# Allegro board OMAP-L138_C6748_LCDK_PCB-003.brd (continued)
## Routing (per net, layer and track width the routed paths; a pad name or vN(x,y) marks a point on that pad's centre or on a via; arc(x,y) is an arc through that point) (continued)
DDR_DQ0: length 21.6
  TOP w0.121: v1(38.61,32) 37.34,33.27 37.34,37.59 36.43,38.5 35.76,38.5 U17.G8
  LYR3 w0.133: v1(38.61,32) 39.62,30.99 44.45,30.99 46.48,28.96 v1(49.53,28.96)
  BOTTOM w0.121: R107.1 v1(49.53,28.96)
DDR_DQ1: length 21.5
  TOP w0.254: v1(40.56,38.5) U17.G2
  LYR3 w0.133: v1(49.53,29.97) 51.05,31.5 51.05,37.97 50.93,38.1 45.72,38.1 44.83,38.99 43.94,38.99 43.43,38.48 42.04,38.48 41.48,39.04 41.1,39.04 v1(40.56,38.5)
  BOTTOM w0.121: R108.1 v1(49.53,29.97)
DDR_DQ2: length 21
  TOP w0.121: U17.H7 36.83,39.7 36.96,39.83 36.96,40.39 37.08,40.51 37.59,40.51 37.72,40.39 37.72,33.53 40.39,30.86 44.32,30.86 46.74,28.45 R109.1
DDR_DQ3: length 21.3
  TOP w0.254: U17.H3 v1(39.76,39.3)
  LYR3 w0.121: 41.76,38.1 40.39,38.1 40.16,38.33 40.16,38.9 v1(39.76,39.3)
  LYR3 w0.133: 41.76,38.1 41.76,38.09 44.33,38.09 44.33,38.1 45.17,38.1 45.68,37.59 50.55,37.59 50.67,37.47 50.67,31.75 50.04,31.11 49.66,31.11 49.53,31.24 v1(49.53,32)
  BOTTOM w0.121: R110.1 v1(49.53,32)
DDR_DQ4: length 21.2
  TOP w0.121: U17.H1 41.91,38.75 41.91,32.77 42.04,32.64 42.42,32.64 42.55,32.77 42.55,33.78 42.67,33.91 43.05,33.91 43.18,33.78 43.18,32.77 43.31,32.64 44.45,32.64 44.58,32.51 44.58,32.26 44.45,32.13 42.29,32.13 42.16,32 42.16,31.75 42.29,31.62 45.34,31.62 46.48,30.48 R111.1
DDR_DQ5: length 21.5
  TOP w0.121: R112.1 v1(45.97,32.51)
  TOP w0.254: U17.H9 v1(34.16,39.3)
  LYR3 w0.133: v1(45.97,32.51) 34.04,32.51 33.27,33.27 33.27,38.42 v1(34.16,39.3)
DDR_DQ6: length 21.1
  TOP w0.121: R115.1 45.97,31.5 45.09,32.38 45.09,32.89 44.96,33.02 43.69,33.02 43.56,33.15 43.56,35.81 43.69,35.94 44.96,35.94 45.09,36.07 45.09,36.36 44.96,36.48 43.31,36.48 43.18,36.61 43.18,37.47 43.31,37.59 45.85,37.59 45.97,37.47 v1(45.97,37.08)
  TOP w0.254: v1(41.36,37.7) U17.F1
  LYR3 w0.121: 41.76,37.71 41.36,37.71 v1(41.36,37.7)
  LYR3 w0.133: v1(45.97,37.08) 45.64,37.08 45.02,37.71 41.76,37.71
DDR_DQ7: length 21.4
  TOP w0.121: R116.1 v1(46.74,33.53)
  TOP w0.254: U17.F9 v1(34.16,37.7)
  LYR3 w0.133: v1(46.74,33.53) 46.74,33.15 46.61,33.02 45.47,33.02 45.34,32.89 36.32,32.89 36.2,33.02 36.2,33.15 36.07,33.27 35.81,33.27 35.69,33.15 35.69,33.03 35.56,32.9 35.31,32.9 35.18,33.03 35.18,33.15 35.05,33.27 34.8,33.27 34.67,33.15 34.67,33.03 34.54,32.9 34.28,32.9 33.66,33.53 33.66,37.97 33.78,38.1 34.03,38.1 34.16,37.97 v1(34.16,37.7)
DDR_DQ8: length 21.4
  TOP w0.254: U17.C8 v1(34.96,35.3)
  LYR3 w0.121: v1(34.96,35.3) 35.36,34.9 36.04,34.9 ; 41.76,34.9 40.28,34.9 40.16,35.03 40.16,35.66 40.01,35.81 39.5,35.81
  LYR3 w0.133: 36.04,34.9 36.96,35.81 39.5,35.81 ; 41.76,34.9 41.77,34.89 45.53,34.89 45.59,34.95 46.96,34.95 47.24,34.67 47.24,32.13 47.12,32 v1(46.74,32)
  BOTTOM w0.121: R138.1 49.53,30.99 48.51,32 v1(46.74,32)
DDR_DQ9: length 21.1
  TOP w0.254: v1(40.56,35.3) U17.C2
  LYR3 w0.121: v1(40.56,35.3) 40.96,35.7 41.76,35.7
  LYR3 w0.133: v1(49.53,34.04) 48.39,34.04 48.26,33.91 48.26,30.99 48.13,30.86 46.23,30.86 46.1,30.99 46.1,31.37 46.23,31.5 47.62,31.5 47.75,31.62 47.75,35.2 47.62,35.33 44.81,35.33 44.42,35.71 41.77,35.71 41.76,35.7
  BOTTOM w0.121: R140.1 v1(49.53,34.04)
DDR_DQ10: length 21.4
  TOP w0.254: v1(35.76,36.1) U17.D7
  LYR3 w0.121: 35.36,38.35 35.36,36.5 v1(35.76,36.1) ; 45.19,36.83 44.7,37.32 41.74,37.32 41.72,37.3 39.5,37.3
  LYR3 w0.133: v1(46.74,37.08) 46.23,36.58 45.45,36.58 45.19,36.83 ; 35.36,38.35 35.48,38.48 37.21,38.48 37.34,38.35 37.34,37.72 37.47,37.59 37.85,37.59 37.97,37.72 37.97,38.35 38.1,38.48 39.22,38.48 39.35,38.35 39.35,37.45 39.5,37.3
  BOTTOM w0.121: R224.1 49.53,38.1 48.51,37.08 v1(46.74,37.08)
DDR_DQ11: length 21.5
  TOP w0.121: U17.D3 38.48,35.62 38.48,33.78 40.25,32.01 v1(40.64,32.01)
  LYR3 w0.133: v1(40.64,32.01) 40.13,32.01 40.01,31.88 40.01,31.5 40.13,31.37 44.61,31.37 46.64,29.34 48.77,29.34 49.02,29.58 49.02,32.51 v1(49.53,33.02)
  BOTTOM w0.121: R225.1 v1(49.53,33.02)
DDR_DQ12: length 21.5
  TOP w0.254: v1(41.36,36.1) U17.D1
  LYR3 w0.121: 41.76,36.1 v1(41.36,36.1)
  LYR3 w0.133: 41.76,36.1 44.54,36.1 44.98,35.66 46.75,35.66 46.8,35.71 48.13,35.71 48.26,35.59 48.26,34.67 48.39,34.54 48.9,34.54 49.02,34.67 49.02,36.45 49.15,36.58 50.16,36.58 50.29,36.7 R226.1 50.16,37.21 47.62,37.21 47.5,37.08 47.5,36.7 47.37,36.58 46.86,36.58 46.74,36.45 v1(46.74,36.1)
  BOTTOM w0.121: R226.1 49.53,37.08 48.55,36.1 v1(46.74,36.1)
DDR_DQ13: length 21.4
  TOP w0.121: R227.1 46.48,36.58 v1(45.97,36.07)
  TOP w0.254: U17.D9 v1(34.16,36.1)
  LYR3 w0.121: 41.66,36.49 41.65,36.5 39.58,36.5 ; v1(34.16,36.1) 34.56,35.7 36.16,35.7
  LYR3 w0.133: 36.16,35.7 36.28,35.83 36.28,37.97 36.41,38.1 36.7,38.1 36.83,37.97 36.83,36.45 36.96,36.32 38.35,36.32 38.48,36.45 38.48,37.97 38.61,38.1 38.86,38.1 38.99,37.97 38.99,36.63 39.12,36.5 39.58,36.5 ; 41.66,36.49 43.99,36.49 44.79,36.49 45.21,36.07 v1(45.97,36.07)
DDR_DQ14: length 21.5
  TOP w0.254: v1(41.36,34.5) U17.B1
  LYR3 w0.121: 41.76,34.5 v1(41.36,34.5)
  LYR3 w0.133: v1(45.97,34.54) 45.93,34.5 41.76,34.5
  BOTTOM w0.121: v1(45.97,34.54) 45.97,35.43 46.1,35.56 47.37,35.56 47.5,35.43 47.5,32.64 47.62,32.51 47.88,32.51 48.01,32.64 48.01,35.43 48.13,35.56 48.39,35.56 48.51,35.43 48.51,32.64 48.64,32.51 48.9,32.51 49.02,32.64 49.02,34.92 49.15,35.05 R228.1
DDR_DQ15: length 21.4
  TOP w0.121: v1(45.97,33.53) 44.78,33.53 44.7,33.6 44.7,33.83 44.78,33.91 45.39,33.91 45.47,33.99 45.47,34.21 45.39,34.29 44.91,34.29 44.83,34.37 44.83,34.72 44.91,34.8 45.39,34.8 45.47,34.87 45.47,35.1 45.39,35.18 44.78,35.18 44.7,35.26 44.7,35.48 44.78,35.56 R229.1
  TOP w0.254: U17.B9 v1(34.16,34.5)
  LYR3 w0.121: 36.8,33.3 36,34.1 34.56,34.1 v1(34.16,34.5)
  LYR3 w0.133: 36.8,33.3 36.83,33.27 44.96,33.27 45.21,33.53 v1(45.97,33.53)
DDR_DQGATE0: length 28.3
  TOP w0.254: v1(56.56,36.9) U7.R11
  LYR3 w0.121: v1(56.56,36.9) 56.16,37.3 55.59,37.3 55.36,37.53 55.36,37.87 53.76,39.47
  LYR3 w0.133: 53.76,39.47 52.58,40.65 52.58,45.47 49.02,49.02 38.35,49.02 38.1,48.77 38.1,48.51 38.23,48.39 v1(38.27,48.39)
  BOTTOM w0.121: R53.1 v1(38.27,48.39)
DDR_DQGATE1: length 29.7
  TOP w0.254: v1(57.36,36.9) U7.R12
  LYR3 w0.121: 53.76,39.84 55.5,38.1 55.88,38.1 55.93,38.1 56.66,37.36 56.9,37.36 v1(57.36,36.9)
  LYR3 w0.133: 53.76,39.84 52.83,40.77 52.83,45.59 49.15,49.28 38.14,49.28 v1(37.25,48.39)
  BOTTOM w0.121: R53.2 v1(37.25,48.39)
DDR_DQM0: length 21.4
  TOP w0.121: R136.2 46.48,29.46 44.7,31.24 40.51,31.24 38.1,33.66 38.1,40.39 38.23,40.51 38.61,40.51 38.73,40.39 38.73,38.23 38.86,38.1 U17.F3
DDR_DQM1: length 21.4
  TOP w0.121: U17.B3 38.99,34.9 38.86,34.77 38.86,33.91 40.01,32.77 40.64,32.77 v1(41.4,32)
  LYR3 w0.133: v1(41.4,32) 44.51,32 46.04,30.48 47.37,30.48 47.5,30.35 47.5,29.84 47.62,29.72 48.51,29.72 48.64,29.84 48.64,32.93 49.23,33.53 49.78,33.53 50.04,33.78 50.04,35.56 v1(49.53,36.07)
  BOTTOM w0.121: R135.2 v1(49.53,36.07)
DDR_DQS0: length 21.1
  TOP w0.121: U17.F7 36.96,37.3 36.96,32.77 39.24,30.48 44.2,30.48 46.86,27.81 49.4,27.81 v1(49.53,27.94)
  BOTTOM w0.121: R134.2 v1(49.53,27.94)
DDR_DQS1: length 21.5
  TOP w0.121: R133.2 v1(46.74,34.54)
  TOP w0.254: v1(35.76,34.5) U17.B7
  LYR3 w0.121: 41.83,34.1 40.13,34.1
  LYR3 w0.133: 40.13,34.1 39.94,34.29 39.48,34.29 39.35,34.42 39.35,35.33 39.24,35.43 38.99,35.43 38.86,35.31 38.86,33.78 38.73,33.66 38.48,33.66 38.35,33.78 38.35,35.31 38.23,35.43 37.97,35.43 37.85,35.31 37.85,33.78 37.72,33.66 37.47,33.66 37.34,33.78 37.34,35.05 37.21,35.18 36.96,35.18 36.83,35.05 36.83,34.42 36.7,34.29 36.41,34.29 36.2,34.5 v1(35.76,34.5) ; v1(46.74,34.54) 46.74,34.23 46.61,34.11 43.31,34.11 43.18,33.98 43.18,33.78 43.05,33.66 42.42,33.66 42.29,33.78 42.29,33.98 42.16,34.11 41.83,34.11 41.83,34.1
DDR_RASN: length 18.8
  TOP w0.121: v1(45.97,38.61) 46.99,37.59 R128.2
  TOP w0.254: v1(35.76,41.7) U17.K7
  LYR3 w0.133: v1(45.97,38.61) 46.48,39.12 47.5,39.12 47.75,39.36 47.75,40.77 47.37,41.15 44.7,41.15 43.94,41.91 40.39,41.91 40.13,42.16 39.5,42.16 39.03,41.7 v1(35.76,41.7)
DDR_VREF: length 30.4
  TOP w0.254: v1(40.56,40.9) U17.J2 ; v1(56.56,41.7) U7.R6
  BOTTOM w0.457: 38.27,40.3 C119.1 R123.2 ; 38.27,40.3 R124.1 C136.2 39.05,42.1 39.37,42.42 43.69,42.42 45.21,43.94 45.21,47.37 47.37,49.53 52.32,49.53 54.16,47.69 v1(54.16,46.5) ; 38.27,40.3 40.31,40.3 40.56,40.54 v1(40.56,40.9)
DDR_WEN: length 18.7
  TOP w0.254: U17.K3 v1(39.76,41.7)
  LYR3 w0.121: 40.96,40.77 40.96,41.15
  LYR3 w0.133: v1(39.76,41.7) 39.93,41.53 40.77,41.53 40.96,41.34 40.96,41.15 ; 40.96,40.77 40.96,40.58 41.15,40.39 41.66,40.39 41.78,40.51 41.78,41.45 41.86,41.53 42.09,41.53 42.16,41.45 42.16,40.46 42.24,40.39 42.47,40.39 42.55,40.46 42.55,41.45 42.62,41.53 42.85,41.53 42.93,41.45 42.93,40.46 43,40.39 43.23,40.39 43.31,40.46 43.31,41.45 43.38,41.53 43.61,41.53 43.69,41.45 43.69,40.51 43.81,40.39 45.72,40.39 v1(45.97,40.64)
  BOTTOM w0.121: v1(45.97,40.64) 46.48,40.13 R129.2
DSP_CLKOUT: length 2
  TOP w0.121: TP10.1 55.63,21.08 R60.1
DSP_RSTOUTN: length 29
  TOP w0.121: v1(56.56,26.42) 57.15,27.01 57.15,27.56 57.78,28.19 66.29,28.19 68.07,26.42 70.36,26.42 73.98,30.04 U11.1
  TOP w0.254: v1(55.76,32.1) U7.T17
  BOTTOM w0.121: v1(56.56,26.42) 55.88,27.1 55.88,29.78 55.76,29.9 v1(55.76,32.1)
EMA_A0: length 51.1
  TOP w0.254: v1(66.96,34.5) U7.C14
  LYR3 w0.121: 68.96,34.5 v1(66.96,34.5)
  LYR3 w0.133: 68.96,34.5 71.59,34.5 71.59,34.51 71.93,34.51 71.94,34.5 74.04,34.5 74.25,34.29 v1(87.88,34.29)
  LYR4 w0.133: v1(87.88,34.29) 88.52,33.66 88.52,29.46 88.65,29.34 90.81,29.34 90.93,29.46 90.93,34.16 91.06,34.29 93.73,34.29 93.85,34.42 93.85,36.45 93.73,36.58 91.19,36.58 91.06,36.45 91.06,35.69 90.93,35.56 90.65,35.56 90.53,35.69 90.53,42.19 J14.21
EMA_A1: length 51.9
  TOP w0.121: v1(82.04,36.32) 82.55,36.83 90.68,36.83 v1(90.93,37.08)
  TOP w0.254: U18.C4 v1(80.96,52.5) ; v1(66.16,33.7) U7.D15
  LYR4 w0.133: J14.22 90.93,42.04 v1(90.93,37.08)
  BOTTOM w0.121: v1(66.16,33.7) 66.21,33.7 66.61,34.1 67.13,34.1 68.08,35.05 71.88,35.05 73.15,33.78 79.5,33.78 v1(82.04,36.32) ; J14.22 90.93,44.32 89.53,44.32 85.09,48.77 85.09,51.56 83.75,52.9 81.36,52.9 v1(80.96,52.5)
EMA_A2: length 54
  TOP w0.121: U7.B14 67.76,34.5 68.75,34.5 68.98,34.28 68.98,32.51 69.1,32.38 72.42,32.38 72.63,32.59 72.63,35.67 74.3,37.34 76.2,37.34 76.45,37.08 90.17,37.08 91.06,37.97 91.06,38.48 91.69,39.12 91.69,39.68 90.73,40.64 J14.23
  TOP w0.254: v1(80.16,53.3) U18.D5
  LYR3 w0.121: v1(80.16,53.3) 79.76,52.9 79.76,52.1
  LYR3 w0.133: v1(84.33,50.8) 84.33,50.83 83.34,51.82 80.04,51.82 79.76,52.1
  BOTTOM w0.121: J14.23 88.39,41.78 88.39,44.58 84.33,48.64 v1(84.33,50.8)
EMA_A3: length 52.5
  TOP w0.121: v1(87.88,33.53) 88.39,33.02 88.39,29.34 88.52,29.21 94.36,29.21 94.49,29.34 94.49,37.97 94.36,38.1 93.98,38.1 93.85,37.97 93.85,35.18 93.73,35.05 93.34,35.05 93.22,35.18 93.22,39.5 J14.24
  TOP w0.254: v1(66.16,34.5) U7.D14
  LYR3 w0.121: v1(66.16,34.5) 66.39,34.5 66.79,34.1 66.95,34.1 68.96,34.1
  LYR3 w0.133: 68.96,34.1 69.28,34.1 69.72,33.66 72.01,33.66 72.39,34.04 87.38,34.04 v1(87.88,33.53)
EMA_A4: length 50
  TOP w0.121: U7.A14 72.06,34.9 72.14,34.82 72.14,34.62 72.06,34.54 69.29,34.54 69.22,34.47 69.22,34.39 69.22,34.38 69.22,34.23 69.29,34.16 71.27,34.16 71.35,34.09 71.35,33.86 71.27,33.78 69.3,33.78 69.22,33.71 69.22,32.77 69.35,32.64 71.17,32.64 71.25,32.72 71.25,32.94 71.17,33.02 69.67,33.02 69.6,33.1 69.6,33.32 69.67,33.4 72.3,33.4 72.38,33.48 72.38,35.8 74.17,37.59 76.45,37.59 76.71,37.34 88.39,37.34 88.52,37.47 88.52,38.99 88.39,39.12 87.83,39.12 87.76,39.19 87.76,39.55 87.83,39.62 91.33,39.62 91.44,39.51 91.44,39.35 91.33,39.24 90.37,39.24 90.3,39.17 90.3,38.94 90.37,38.86 90.73,38.86 90.81,38.79 90.81,38.23 90.68,38.1 J14.25
EMA_A5: length 51.5
  TOP w0.254: v1(66.96,35.3) U7.C13
  LYR3 w0.121: v1(66.96,35.3) 68.58,35.3 68.71,35.43 68.71,37.85 68.96,38.1
  LYR3 w0.133: J14.26 92.08,36.96 92.2,36.83 93.85,36.83 93.98,36.7 93.98,32.13 93.85,32 93.73,32 93.6,32.13 93.6,36.2 93.47,36.32 93.22,36.32 93.09,36.2 93.09,32.13 92.96,32 90.81,32 90.68,32.13 90.68,35.94 89.92,36.7 88.77,36.7 88.35,37.12 72.39,37.12 72.26,37.25 72.26,37.97 72.14,38.1 71.94,38.1 71.93,38.11 71.59,38.11 71.59,38.1 69.54,38.1 69.53,38.11 69.19,38.11 69.19,38.1 68.96,38.1
EMA_A6: length 51.6
  TOP w0.254: v1(65.36,35.3) U7.E13
  LYR3 w0.121: v1(65.36,35.3) 65.76,34.9 67.28,34.9 67.31,34.92 68.96,34.92
  LYR3 w0.133: 68.96,34.92 74.04,34.92 74.17,35.05 74.17,35.43 74.04,35.56 69.22,35.56 69.09,35.69 69.09,35.94 69.22,36.07 69.72,36.07 69.85,36.2 69.85,37.72 69.98,37.85 70.23,37.85 70.36,37.72 70.36,36.14 70.43,36.07 70.66,36.07 70.74,36.14 70.74,37.72 70.87,37.85 71.12,37.85 71.25,37.72 71.25,36.2 71.37,36.07 78.11,36.07 78.23,35.94 78.23,35.18 78.11,35.05 74.8,35.05 74.68,34.92 74.68,34.67 74.8,34.54 87.25,34.54 87.5,34.8 87.5,35.31 87.76,35.56 J14.27
EMA_A7: length 50.9
  TOP w0.121: v1(87.88,38.35) 87.88,37.72 87.76,37.59 76.96,37.59 76.71,37.85 74.04,37.85 72.14,35.94 72.14,35.91 72.13,35.91 72.13,35.42 72.01,35.3 67.76,35.3 U7.B13
  BOTTOM w0.121: v1(87.88,38.35) 87.88,39.04 87.96,39.12 90.6,39.12 90.68,39.04 90.68,37.67 90.75,37.59 90.98,37.59 91.06,37.67 91.06,39.04 91.14,39.12 93.22,39.12 93.47,38.86 93.47,31.57 93.4,31.5 93.17,31.5 93.09,31.57 93.09,33.96 93.01,34.04 91.52,34.04 91.44,34.11 91.44,34.47 91.52,34.54 93.01,34.54 93.09,34.62 93.09,37.01 93.01,37.08 92.15,37.08 92.08,37.01 J14.28
EMA_A8: length 50.3
  TOP w0.121: v1(86.36,38.35) 86.36,38.48 86.23,38.61 78.56,38.61 78.49,38.53 78.49,38.3 78.56,38.23 85.78,38.23 85.85,38.15 85.85,37.92 85.78,37.85 77.55,37.85 77.47,37.92 77.47,38.53 77.39,38.61 77.17,38.61 77.09,38.53 77.09,38.18 77.01,38.1 76.78,38.1 76.71,38.18 76.71,38.53 76.63,38.61 76.4,38.61 76.33,38.53 76.33,38.18 76.25,38.1 76.02,38.1 75.95,38.18 75.95,38.53 75.87,38.61 75.64,38.61 75.56,38.53 75.56,38.18 75.49,38.1 75.26,38.1 75.18,38.18 75.18,38.53 75.11,38.61 74.93,38.61 74.42,38.1 73.36,38.1 73.28,38.02 73.28,37.54 73.2,37.47 73.1,37.47 73.03,37.54 73.03,38.02 72.95,38.1 72.85,38.1 72.77,38.02 72.77,37.16 72.69,37.08 72.59,37.08 72.52,37.16 72.52,38.02 72.44,38.1 72.34,38.1 72.26,38.02 72.26,37.16 72.19,37.08 71.32,37.08 71.25,37.01 71.25,36.02 71.32,35.94 71.81,35.94 71.88,35.86 71.88,35.64 71.81,35.56 68.74,35.56 68.6,35.7 U7.A13
  BOTTOM w0.121: v1(86.36,38.35) 86.36,37.85 88.39,35.81 88.39,35.18 89.53,34.04 J14.29
EMA_A9: length 52.2
  TOP w0.254: v1(66.16,36.1) U7.D12
  LYR3 w0.121: v1(66.16,36.1) 66.56,35.7 68.33,35.7 68.45,35.83 68.45,38.23 68.58,38.35 68.96,38.35
  LYR3 w0.133: 68.96,38.35 76.07,38.35 76.2,38.23 76.2,37.97 76.07,37.85 72.77,37.85 72.64,37.72 72.64,37.48 72.77,37.36 77.12,37.36 77.12,37.36 77.31,37.36 77.31,37.36 78.76,37.36 80.26,38.86 88.39,38.86 88.52,38.73 88.52,37.97 88.39,37.85 83.44,37.85 83.31,37.72 83.31,37.48 83.44,37.36 88.63,37.36 88.9,37.08 90.04,37.08 91.06,36.07 91.06,34.04 J14.30
EMA_A10: length 51
  TOP w0.254: v1(66.96,36.1) U7.C12
  LYR3 w0.121: v1(66.96,36.1) 66.96,36.96 67.09,37.08 68.07,37.08 68.2,37.21 68.2,38.42 68.39,38.61 68.96,38.61
  LYR3 w0.133: J14.31 90.55,31.5 94.74,31.5 94.87,31.62 94.87,33.91 95,34.04 96.39,34.04 96.52,34.16 96.52,34.42 96.39,34.54 95,34.54 94.87,34.67 94.87,36.45 95,36.58 96.39,36.58 96.52,36.7 96.52,36.96 96.39,37.08 95,37.08 94.87,37.21 94.87,38.99 94.74,39.12 80.01,39.12 78.49,37.59 77.22,37.59 76.2,38.61 68.96,38.61
EMA_A11: length 51.7
  TOP w0.121: v1(87.12,38.35) 87.12,38.73 87,38.86 74.68,38.86 74.17,38.35 71.7,38.35 70.87,37.52 70.87,36.83 69.85,35.81 68.87,35.81 68.58,36.1 67.76,36.1 U7.B12
  BOTTOM w0.121: J14.32 93.85,30.48 93.98,30.35 93.98,23.5 93.85,23.37 93.34,23.37 93.22,23.5 93.22,26.29 93.09,26.42 91.19,26.42 91.06,26.54 91.06,36.33 90.81,36.58 88.39,36.58 87.12,37.85 v1(87.12,38.35)
EMA_A12: length 52.5
  TOP w0.254: v1(66.16,35.3) U7.D13
  LYR4 w0.133: v1(81.28,36.32) 80.64,35.69 80.64,19.3 80.9,19.05 87.63,19.05 87.88,19.3 87.88,27.69 88.14,27.94 J14.33
  BOTTOM w0.121: v1(66.16,35.3) 66.56,34.9 67.13,34.9 67.53,35.31 72.14,35.31 73.41,34.04 79.25,34.04 81.28,36.07 v1(81.28,36.32)
EMA_BA_0: length 51
  TOP w0.254: v1(66.96,33.7) U7.C15
  LYR3 w0.121: v1(66.96,33.7) 67.36,33.3 67.36,30.18 67.44,30.1
  LYR3 w0.133: J14.37 89.53,23.75 89.41,23.88 83.69,23.88 83.57,24 83.57,24.26 83.69,24.38 93.34,24.38 93.47,24.51 93.47,26.29 93.34,26.42 83.82,26.42 82.3,27.94 73.41,27.94 71.88,29.46 68.07,29.46 67.44,30.1
EMA_BA_1: length 51.2
  TOP w0.254: v1(68.56,33.7) U7.A15
  LYR3 w0.121: v1(68.56,33.7) 68.96,33.7
  LYR3 w0.133: 68.96,33.7 69.17,33.7 70.61,32.26 72.26,32.26 72.39,32.38 72.39,33.4 72.52,33.53 82.42,33.53 82.55,33.4 82.55,32.64 82.42,32.51 73.41,32.51 73.28,32.38 73.28,31.75 73.41,31.62 77.6,31.62 77.98,31.24 81.79,31.24 82.42,31.88 87,31.88 v1(87.88,32.77)
  BOTTOM w0.121: v1(87.88,32.77) 87.38,32.26 87.38,27.18 89.15,25.4 J14.35
EMA_CLK: length 51.4
  TOP w0.121: U7.B7 67.76,40.9 68.43,40.9 68.89,41.36 69.43,41.36 71.37,43.31 73.15,43.31 73.28,43.43 74.17,43.43 75.44,44.7 79.76,44.7 v1(80.77,43.69)
  BOTTOM w0.121: v1(80.77,43.69) 80.77,40.89 80.42,40.54 80.42,39.72 82.04,38.1 83.06,38.1 84.84,36.32 84.84,27.18 85.6,26.42 86.87,26.42 87.63,25.65 87.63,17.78 88.9,16.51 90.81,16.51 J14.42
EMA_CSN_2: length 51.2
  TOP w0.254: v1(67.76,32.1) U7.B17
  LYR3 w0.121: v1(67.76,32.1) 68.16,31.7 68.96,31.7
  LYR3 w0.133: J14.40 93.73,20.32 93.85,20.45 93.85,21.21 93.73,21.34 88.65,21.34 88.52,21.46 88.52,21.72 88.65,21.84 93.73,21.84 93.85,21.97 93.85,29.08 93.73,29.21 82.55,29.21 81.79,29.97 71.32,29.97 69.6,31.7 68.96,31.7
  BOTTOM w0.121: v1(67.76,32.1) 68.16,31.7 68.73,31.7 R103.2
EMA_CSN_3: length 51.9
  TOP w0.121: v1(68.56,32.1) 71.57,32.1 71.59,32.12 72.5,32.12 72.88,32.49 72.88,35.54 74.42,37.08 75.44,37.08 v1(75.95,36.58)
  TOP w0.254: v1(78.56,52.5) U18.C6 ; v1(68.56,32.1) U7.A17
  BOTTOM w0.121: R106.2 69.36,32.9 v1(68.56,32.1) ; v1(75.95,36.58) 75.95,39.5 75.82,39.62 75.56,39.62 75.44,39.5 75.44,37.21 75.31,37.08 75.06,37.08 74.93,37.21 74.93,40.13 75.06,40.26 75.31,40.26 75.44,40.39 75.44,44.45 75.95,44.96 75.95,56.52 76.07,56.64 76.33,56.64 76.45,56.52 76.45,53.21 76.58,53.09 76.96,53.09 77.09,53.21 77.09,54.23 77.22,54.36 77.47,54.36 77.6,54.23 77.6,53.21 77.72,53.09 77.98,53.09 78.11,53.21 78.11,54.23 78.23,54.36 78.44,54.36 78.56,54.23 v1(78.56,52.5)
EMA_CSN_4: length 49.8
  TOP w0.254: v1(64.56,39.3) U7.F9
  LYR3 w0.121: v1(64.56,39.3) 64.96,38.9 67.47,38.9 67.94,39.37 68.96,39.37
  LYR3 w0.133: v1(81.28,40.13) 80.77,40.64 75.82,40.64 75.31,40.13 73.15,40.13 72.39,39.37 68.96,39.37
  LYR4 w0.133: v1(85.6,45.72) 86.36,46.48 86.36,56.9 89.15,59.69 94.61,59.69 J15.7
  BOTTOM w0.121: v1(81.28,40.13) 81.79,40.64 81.79,44.2 82.55,44.96 84.84,44.96 v1(85.6,45.72)
EMA_CSN_5: length 54.1
  TOP w0.254: v1(67.76,32.9) U7.B16
  LYR4 w0.133: J15.3 95.89,65.66 92.46,62.23 89.15,62.23 86.11,59.18 86.11,47.24 83.06,44.2 83.06,36.58 v1(82.04,35.56)
  BOTTOM w0.121: v1(67.76,32.9) 67.76,32.96 68.1,33.3 69.09,33.3 69.32,33.53 80.01,33.53 v1(82.04,35.56)
EMA_D0: length 57
  TOP w0.121: U18.H4 80.15,56.49 80.15,55.94 79.92,55.71 76.03,55.71 v1(75.18,54.86)
  TOP w0.254: U18.H4 v1(80.96,57.3) ; v1(66.96,39.3) U7.C9
  LYR3 w0.121: 82.16,55.87 80.96,57.07 v1(80.96,57.3)
  LYR3 w0.133: J14.3 90.81,64.77 92.46,64.77 93.73,63.5 93.73,55.88 92.54,54.69 88.57,54.69 87.63,55.63 82.4,55.63 82.16,55.87
  LYR4 w0.121: 68.96,40.77 67.49,39.3 v1(66.96,39.3)
  LYR4 w0.133: v1(75.18,54.86) 75.18,55.24 75.31,55.37 75.82,55.37 75.95,55.24 75.95,54.61 75.44,54.1 74.17,54.1 70.61,50.55 70.61,42.42 68.96,40.77
EMA_D1: length 57.1
  TOP w0.121: U7.A8 68.37,39.7 69.19,40.52 69.98,40.52 70.88,41.42 73.17,41.42 v1(73.66,41.91)
  TOP w0.254: U18.J4 v1(80.96,58.1)
  LYR3 w0.121: v1(80.96,58.1) U18.J4 80.56,56.22 81.41,55.37 82.16,55.37
  LYR3 w0.133: 82.16,55.37 87.38,55.37 88.29,54.45 92.81,54.45 93.98,55.63 93.98,64.14 J14.4
  LYR4 w0.121: v1(80.96,58.1) 81.36,57.7 81.36,52.11 81.38,52.1
  LYR4 w0.133: 81.38,52.1 81.79,51.69 81.79,50.29 80.26,48.77 77.72,48.77 75.18,46.23 75.18,43.43 75.44,43.18 75.44,42.67 75.18,42.42 74.17,42.42 v1(73.66,41.91)
EMA_D2: length 51.5
  TOP w0.121: U7.B8 67.76,40.1 68.42,40.1 69.09,40.76 69.72,40.76 71.37,42.42 74.42,42.42 v1(74.93,42.93)
  TOP w0.254: U18.K4 v1(80.96,58.9)
  LYR3 w0.133: v1(80.96,58.9) 81.5,59.44 85.85,59.44 88.14,57.15 92.46,57.15 93.22,57.91 93.22,61.72 92.46,62.48 90.55,62.48 J14.5
  LYR4 w0.121: v1(80.96,58.9) U18.K4 80.56,52.1
  LYR4 w0.133: v1(74.93,42.93) 74.93,46.48 77.47,49.02 80.14,49.02 80.64,49.53 80.64,52.02 80.56,52.1
EMA_D3: length 51.9
  TOP w0.121: U18.K5 78.57,59.69 76.4,59.69 76.17,59.46 76.17,57.88 74.42,56.13 v1(74.42,54.86)
  TOP w0.254: v1(80.16,58.9) U18.K5 ; v1(65.36,40.1) U7.E8
  LYR3 w0.121: 82.16,58.5 80.8,58.5 80.4,58.9 v1(80.16,58.9)
  LYR3 w0.133: 82.16,58.5 86.28,58.5 87.88,56.9 92.71,56.9 93.47,57.66 93.47,62.1 J14.6
  LYR4 w0.121: v1(65.36,40.1) 65.76,39.7 67.51,39.7 68.96,41.15
  LYR4 w0.133: v1(74.42,54.86) 70.36,50.8 70.36,42.55 68.96,41.15
EMA_D4: length 45.8
  TOP w0.254: v1(78.56,58.9) U18.K6 ; v1(67.76,42.5) U7.B5
  LYR3 w0.133: v1(78.56,58.9) 78.56,60.02 78.99,60.45 86.36,60.45 87.12,59.69 90.68,59.69 90.93,59.94 90.93,60.71 90.68,60.96 J14.7
  LYR4 w0.121: v1(78.56,58.9) 78.56,59.3 ; v1(67.76,42.5) 68.15,42.5 68.96,43.31
  LYR4 w0.133: 78.56,59.3 78.56,60.2 78.31,60.45 71.37,60.45 70.36,59.44 70.36,53.34 69.09,52.07 69.09,43.43 68.96,43.31
EMA_D5: length 48.6
  TOP w0.254: v1(65.36,40.9) U7.E7 ; U18.J7 v1(77.76,58.1)
  LYR3 w0.121: v1(77.76,58.1) 77.36,58.5 77.36,59.3
  LYR3 w0.133: J14.8 91.06,61.98 88.65,61.98 87.38,60.71 78.74,60.71 77.36,59.33 77.36,59.3
  LYR4 w0.121: 76.56,56.92 76.57,56.9 77.93,56.9 78.16,57.14 U18.J7 v1(77.76,58.1) ; 68.96,41.53 67.93,40.5 65.76,40.5 v1(65.36,40.9)
  LYR4 w0.133: 76.56,56.92 75.56,57.91 71.63,57.91 71.37,57.66 71.37,52.32 70.1,51.05 70.1,42.67 68.96,41.53
EMA_D6: length 44.3
  TOP w0.254: U18.K7 v1(77.76,58.9) ; v1(66.96,41.7) U7.C6
  LYR3 w0.121: v1(77.76,58.9) U18.K7 78.82,58.5 78.99,58.67 78.99,59.3
  LYR3 w0.133: 78.99,59.3 78.96,59.34 78.96,59.91 79.25,60.2 86.11,60.2 87.88,58.42 J14.9
  LYR4 w0.121: 77.98,60.2 78.23,59.94 78.23,59.37 v1(77.76,58.9) ; 68.96,42.8 68.26,42.1 67.37,42.1 66.97,41.7 v1(66.96,41.7)
  LYR4 w0.133: 68.96,42.8 69.34,43.18 69.34,51.82 70.61,53.09 70.61,59.31 71.5,60.2 77.98,60.2
EMA_D7: length 47.9
  TOP w0.254: U18.J8 v1(76.96,58.1) ; v1(66.16,40.9) U7.D7
  LYR3 w0.121: 79.88,59.3 79.5,58.93 79.5,58.17 79.04,57.7 U18.J8 v1(76.96,58.1)
  LYR3 w0.133: 79.88,59.3 80.26,59.69 86.11,59.69 88.39,57.4 91.06,57.4 J14.10
  LYR4 w0.121: 67.13,41.3 66.56,41.3 v1(66.16,40.9)
  LYR4 w0.133: 67.13,41.3 67.15,41.27 67.94,41.27 69.6,42.93 69.6,51.56 70.85,52.81 70.85,59.16 71.63,59.94 76.07,59.94 76.45,59.56 76.45,58.61 v1(76.96,58.1)
EMA_D8: length 42
  TOP w0.121: U18.H3 81.75,56.51 81.75,55.14 81.52,54.91 78.82,54.91 78.57,54.66 78.57,54.34 78.33,54.1 75.69,54.1 v1(74.42,52.83)
  TOP w0.254: v1(65.36,38.5) U7.E10 ; U18.H3 v1(81.76,57.3)
  LYR3 w0.121: v1(81.76,57.3) 82.16,56.9
  LYR3 w0.133: J14.11 88.39,55.88 86.11,58.17 85.34,58.17 83.44,56.26 82.8,56.26 82.16,56.9
  LYR4 w0.121: 68.96,40.39 67.47,38.9 65.76,38.9 v1(65.36,38.5)
  LYR4 w0.133: 68.96,40.39 70.87,42.29 70.87,50.29 74.04,53.47 74.3,53.47 74.42,53.34 v1(74.42,52.83)
EMA_D9: length 45.5
  TOP w0.121: v1(81.76,58.1) 82.3,57.57 82.3,54.86 81.52,54.09 79.6,54.09 79.37,53.86 79.37,53.56 79.12,53.31 75.92,53.31 v1(74.42,51.82)
  TOP w0.254: U18.J3 v1(81.76,58.1) ; v1(66.16,38.5) U7.D9
  LYR3 w0.121: v1(81.76,58.1) U18.J3 81.36,57.07 82.16,56.27
  LYR3 w0.133: 82.16,56.27 82.55,55.88 87.88,55.88 88.84,54.92 91.12,54.92 J14.12
  LYR4 w0.121: v1(66.16,38.5) 66.16,38.49 66.55,38.1 67.31,38.1 68.83,39.62 68.96,39.62
  LYR4 w0.133: v1(74.42,51.82) 71.12,48.51 71.12,42.04 70.1,41.02 70.1,40.13 69.6,39.62 68.96,39.62
EMA_D10: length 45.4
  TOP w0.121: U7.A7 68.47,40.5 68.98,41.01 69.59,41.01 71.41,42.83 73.42,42.83 73.52,42.93 v1(73.66,42.93)
  TOP w0.254: v1(80.16,57.3) U18.H5
  LYR3 w0.121: 82.16,55.12 81.28,55.12 80.16,56.24 v1(80.16,57.3)
  LYR3 w0.133: J14.13 90.68,53.34 90.93,53.09 90.93,52.58 90.42,52.07 88.9,52.07 85.85,55.12 82.16,55.12
  LYR4 w0.121: v1(80.16,57.3) 80.16,56.26 80.04,56.13 79.76,56.13 79.63,56.26 79.63,57.18 79.5,57.3 79.38,57.3 79.25,57.18 79.25,56.01 79.38,55.88 79.5,55.88 79.63,55.75 79.63,52.32 79.85,52.1
  LYR4 w0.133: 79.85,52.1 80.39,51.56 80.39,49.66 80.07,49.34 77.28,49.34 74.68,46.74 74.68,43.56 74.04,42.93 v1(73.66,42.93)
EMA_D11: length 48.2
  TOP w0.254: v1(80.16,58.1) U18.J5 ; v1(66.16,41.7) U7.D6
  LYR3 w0.121: v1(66.16,41.7) 66.56,41.3 68.1,41.3 68.96,42.16 ; v1(80.16,58.1) 80.16,58.06 79.76,57.66 79.76,56.26 81.15,54.86 82.16,54.86
  LYR3 w0.133: J14.14 90.55,51.82 88.65,51.82 85.6,54.86 82.16,54.86 ; 68.96,42.16 69.22,42.42 72.14,42.42 v1(72.64,41.91)
  LYR4 w0.121: 79.38,52.1 79.38,55.5 79.25,55.63 79.12,55.63 78.99,55.75 78.99,57.98 79.12,58.1 v1(80.16,58.1)
  LYR4 w0.133: v1(72.64,41.91) 72.64,42.67 73.41,43.43 73.91,43.43 74.42,43.94 74.42,46.99 77.01,49.57 79.88,49.57 80.14,49.83 80.14,51.31 79.38,52.07 79.38,52.1
EMA_D12: length 44.5
  TOP w0.121: v1(72.64,43.94) 72.39,43.69 70.82,43.69 68.84,41.71 68.82,41.71 68.61,41.51 68.61,41.48 68.43,41.3 U7.A6
  TOP w0.254: v1(78.56,57.3) U18.H6
  LYR3 w0.121: 82.16,54.61 81.03,54.61 79.25,56.39 79.25,56.64 78.59,57.3 v1(78.56,57.3)
  LYR3 w0.133: 82.16,54.61 85.34,54.61 89.15,50.8 J14.15
  LYR4 w0.121: v1(78.56,57.3) 78.56,57.07 78.16,56.67 78.16,55.75 78.03,55.63 76.96,55.63 76.83,55.5 76.83,53.21 76.71,53.09 75.69,53.09 75.56,52.96 75.56,51.18
  LYR4 w0.133: v1(72.64,43.94) 73.66,44.96 73.66,49.51 74.31,50.15 78.23,50.15 78.36,50.28 78.36,51.69 78.23,51.82 77.09,51.82 76.96,51.69 76.96,51.18 76.83,51.05 75.69,51.05 75.56,51.18
EMA_D13: length 46.8
  TOP w0.121: v1(67.76,41.7) 68.37,41.7 70.74,44.07 72.14,44.07 72.52,44.45 73.15,44.45 v1(73.66,43.94)
  TOP w0.254: U18.G6 v1(78.56,56.5) ; v1(67.76,41.7) U7.B6
  LYR3 w0.121: v1(78.56,56.5) 80.71,54.36 82.16,54.36
  LYR3 w0.133: 82.16,54.36 83.06,54.36 83.82,53.59 85.85,53.59 88.39,51.05 88.39,50.42 89.03,49.78 91.06,49.78 J14.16
  LYR4 w0.121: v1(78.56,56.5) 78.56,55.37 78.69,55.24 78.87,55.24 78.99,55.12 78.99,52.1
  LYR4 w0.133: 78.99,52.1 78.99,51.94 79.88,51.05 79.88,50.04 79.65,49.81 79.38,49.81 79.25,49.94 79.25,51.05 79.12,51.18 78.87,51.18 78.74,51.05 78.74,49.94 78.61,49.81 74.42,49.81 74.17,49.56 74.17,44.45 v1(73.66,43.94)
EMA_D14: length 47.3
  TOP w0.254: v1(66.96,40.9) U7.C7 ; U18.H7 v1(77.76,57.3)
  LYR3 w0.121: 82.16,53.85 79.76,53.85 77.36,56.24 77.36,56.9 v1(77.76,57.3)
  LYR3 w0.133: 82.16,53.85 82.55,53.85 83.31,53.09 85.34,53.09 87.88,50.55 87.88,49.91 J14.17
  LYR4 w0.121: v1(66.96,40.9) 67.95,40.9 68.96,41.91 ; v1(77.76,57.3) 77.36,57.7 76.66,57.7
  LYR4 w0.133: 68.96,41.91 69.85,42.8 69.85,51.31 71.12,52.58 71.12,59.1 71.71,59.69 75.82,59.69 76.07,59.44 76.07,58.29 76.66,57.7
EMA_D15: length 49.2
  TOP w0.254: U18.G7 77.88,56.39 v1(77.76,56.5) ; v1(65.36,41.7) U7.E6
  LYR3 w0.121: 68.96,41.27 68.19,40.5 65.99,40.5 65.76,40.73 65.76,41.3 65.36,41.7 v1(65.36,41.7) ; v1(77.76,56.5) 80.16,54.1 82.16,54.1
  LYR3 w0.133: v1(71.75,41.91) 71.14,41.3 68.99,41.3 68.96,41.27 ; 82.16,54.1 82.8,54.1 83.57,53.34 85.6,53.34 88.14,50.8 88.14,50.16 89.03,49.28 91.06,49.28 J14.18
  LYR4 w0.121: 74.93,51.56 74.93,53.47 75.06,53.59 76.2,53.59 76.33,53.72 76.33,55.75 76.2,55.88 74.55,55.88 74.42,56.01 74.42,56.38 74.55,56.5 v1(77.76,56.5)
  LYR4 w0.133: 74.93,51.56 73.15,49.78 73.15,47.24 72.64,46.74 72.64,44.7 71.75,43.81 v1(71.75,41.91)
EMA_OEN: length 71.1
  TOP w0.254: U18.D4 v1(80.96,53.3) ; v1(67.76,33.7) U7.B15
  LYR3 w0.121: 68.96,33.3 68.16,33.3 v1(67.76,33.7) ; 82.16,52.83 82.09,52.9 81.36,52.9 v1(80.96,53.3)
  LYR3 w0.133: v1(86.87,50.8) 84.84,52.83 82.16,52.83 ; 68.96,33.3 69.03,33.3 69.04,33.29 69.07,33.29 71.12,31.24 77.22,31.24 77.6,30.86 82.17,30.86 82.8,31.5 87.38,31.5 v1(87.88,32)
  LYR4 w0.133: v1(86.87,50.8) 87.38,50.29 87.38,43.43 85.85,41.91 85.85,38.86 85.09,38.1 85.09,32.77 85.85,32 v1(87.88,32)
  BOTTOM w0.121: v1(87.88,32) 87.88,27.18 88.65,26.42 89.92,26.42 90.55,25.78 90.55,18.8 J14.41 ; R105.2 68.73,34.1 68.16,34.1 v1(67.76,33.7)
EMA_WAIT0: length 31.1
  TOP w0.121: v1(74.93,36.58) 74.42,36.58 73.12,35.28 73.12,31.47 72.77,31.11 70.99,31.11 70.81,31.3 v1(67.76,31.3)
  TOP w0.254: v1(67.76,31.3) U7.B18 ; U18.C8 v1(76.96,52.5)
  BOTTOM w0.121: v1(76.96,52.5) 76.96,51.81 R137.1 76.85,50.95 76.45,50.55 76.45,36.32 76.2,36.07 75.44,36.07 v1(74.93,36.58)
EMA_WAIT1: length 25.9
  TOP w0.254: v1(67.76,30.5) U7.B19
  LYR3 w0.121: 68.16,30.1 v1(67.76,30.5)
  LYR3 w0.133: 68.16,30.1 68.54,29.72 81.28,29.72 82.04,28.96 91.06,28.96 J14.34
EMA_WEN: length 56.8
  TOP w0.121: U7.B9 67.76,39.3 68.32,39.3 69.13,40.1 v1(69.36,40.1)
  TOP w0.254: U18.C7 v1(77.76,52.5)
  LYR3 w0.121: v1(77.76,52.5) 78.16,52.1
  LYR3 w0.133: v1(81.28,50.8) 79.46,50.8 78.16,52.1 ; v1(81.28,41.91) 75.69,41.91 75.18,41.4 71.88,41.4 70.58,40.1 v1(69.36,40.1)
  BOTTOM w0.121: v1(81.28,50.8) v1(81.28,41.91) 81.28,40.89 80.77,40.39 80.77,39.88 82.04,38.61 83.57,38.61 85.34,36.83 85.34,27.18 85.6,26.92 87.12,26.92 88.14,25.91 88.14,21.72 J14.39 ; R104.2 v1(69.36,40.1)
EMA_WEN_DQM_0: length 53.8
  TOP w0.254: v1(66.96,40.1) U7.C8
  LYR3 w0.121: 68.96,39.75 68.61,40.1 v1(66.96,40.1)
  LYR3 w0.133: 68.96,39.75 69.09,39.62 72.14,39.62 72.9,40.39 75.06,40.39 75.56,40.89 85.3,40.89 85.72,40.46 85.72,39.88 86.23,39.37 96.01,39.37 96.9,38.48 96.9,31.88 96.52,31.5 95.38,31.5 94.87,30.99 v1(93.47,30.99)
  BOTTOM w0.121: J14.38 94.11,22.86 94.36,23.11 94.36,30.48 93.85,30.99 v1(93.47,30.99)
EMA_WEN_DQM_1: length 51.3
  TOP w0.121: U7.A5 71.02,44.96 72.39,44.96 72.64,45.21 80.01,45.21 80.64,44.58 86.23,44.58 89.15,41.66 96.39,41.66 97.03,41.02 97.03,27.43 96.27,26.67 93.34,26.67 J14.36
EMU0: length 34
  TOP w0.121: R63.2 R67.2 v1(78.74,35.56)
  TOP w0.254: v1(62.16,32.9) U7.J16
  LYR3 w0.121: 68.96,39.12 68.14,39.12 65.53,36.5 64.95,36.5 64.16,35.71 64.16,34.7 63.75,34.29 62.98,34.29 62.56,33.87 62.56,33.86 62.56,33.35 62.16,32.95 v1(62.16,32.9)
  LYR3 w0.133: v1(77.98,38.35) 77.22,39.12 68.96,39.12 ; J6.13 85.09,36.83 80.01,36.83 v1(78.74,35.56)
  BOTTOM w0.121: v1(77.98,38.35) 77.98,36.32 v1(78.74,35.56)
EMU1: length 27.6
  TOP w0.121: J6.14 83.06,34.8 R62.2 R66.2 v1(80.01,35.56)
  TOP w0.254: v1(60.56,32.9) U7.K16
  BOTTOM w0.121: v1(60.56,32.9) 60.96,32.5 63.93,32.5 64.16,32.73 64.16,33.17 65.76,34.77 65.76,35.53 65.93,35.7 72.25,35.7 72.9,35.05 79.5,35.05 v1(80.01,35.56)
EN_DCDC1: length 16.6
  TOP w0.121: U3.20 v1(30.23,67.82) ; Q2.3 20.32,70.87 20.57,71.12 v1(20.57,71.37)
  BOTTOM w0.121: v1(30.23,67.82) 29.47,68.58 27.43,68.58 26.42,67.56 22.35,67.56 21.34,68.58 21.34,70.61 v1(20.57,71.37) R23.1
EN_DCDC2: length 15.4
  TOP w0.121: v1(30.23,67.06) 29.73,67.55 U3.19 ; Q1.3 20.33,67.06 20.57,67.3 v1(20.57,67.56)
  BOTTOM w0.121: v1(30.23,67.06) 28.96,68.33 27.69,68.33 26.42,67.06 21.08,67.06 v1(20.57,67.56) R22.1
ENET_RXN: length 27.7
  TOP w0.121: U23.30 75.45,74.66 v1(75.18,74.93) 75.18,75.44 R165.2
  LYR3 w0.102: 93.98,80.64 92.89,79.55 91.95,79.55 91.26,78.87 91.26,77.47 89.23,75.44 80.52,75.44 79.04,73.96 75.41,73.96 74.96,74.42 74.96,74.7 v1(75.18,74.93)
  BOTTOM w0.095: C194.1 93.98,80.64
ENET_RXP: length 30.3
  TOP w0.121: v1(74.42,74.93) 74.95,74.4 U23.31
  LYR3 w0.102: J13.7 92.71,78.99 92.46,79.25 92.07,79.25 91.57,78.74 91.57,77.34 89.36,75.13 80.64,75.13 79.17,73.66 75.29,73.66 74.65,74.3 74.65,74.7 v1(74.42,74.93)
  BOTTOM w0.095: C137.1 J13.7
  BOTTOM w0.121: v1(74.42,74.93) 74.42,75.18 R166.2
ENET_TXN: length 19.4
  TOP w0.121: U23.28 76.45,74.67 v1(76.71,74.93) 76.71,75.18 R167.2
  LYR3 w0.102: v1(76.71,74.93) 76.48,75.16 76.48,75.69 76.94,76.15 85.5,76.15 86.41,77.06 86.41,80.59 86.36,80.64
  BOTTOM w0.095: C196.1 86.36,80.64
ENET_TXP: length 21.9
  TOP w0.121: v1(75.95,74.93) 75.95,74.68 U23.29
  LYR3 w0.102: v1(75.95,74.93) 76.17,75.16 76.17,75.82 76.81,76.45 85.37,76.45 86.11,77.19 86.11,78.88 85.85,79.13 85.34,79.13 85.09,78.88 J13.1
  BOTTOM w0.095: C197.1 J13.1
  BOTTOM w0.121: v1(75.95,74.93) 76.2,75.18 R168.2
GLCO/I2CA: length 3.8
  TOP w0.121: v1(42.93,22.86) 43.64,23.57 U21.37
  BOTTOM w0.121: R149.2 R148.1 v1(42.93,22.86)
GPIO: length 6.7
  TOP w0.121: TP12.1 47.24,19.3 47.24,21.72 46.39,22.57 U21.35
GPIO0-1: length 22.7
  TOP w0.121: SW1.5 60.96,54.61 v1(60.45,55.12)
  TOP w0.254: v1(66.96,44.1) U7.C3
  LYR4 w0.121: v1(66.96,44.1) 66.56,44.5 66.56,46.1
  LYR4 w0.133: v1(66.04,55.12) 65.66,54.74 65.66,47.13 66.56,46.23 66.56,46.1
  BOTTOM w0.121: R257.2 v1(66.04,55.12) 65.53,54.61 64.39,54.61 63.37,55.63 60.96,55.63 v1(60.45,55.12)
GPIO0-2: length 17.3
  TOP w0.121: SW1.6 63.5,53.85 v1(64.77,55.12)
  TOP w0.254: v1(66.16,43.3) U7.D4
  LYR4 w0.121: v1(66.16,43.3) 65.76,43.7 65.76,46.1
  LYR4 w0.133: v1(64.77,55.12) 65.41,54.48 65.41,46.61 65.76,46.25 65.76,46.1
  BOTTOM w0.121: v1(64.77,55.12) R258.1
GPIO0-3: length 18.7
  TOP w0.121: v1(67.31,55.12) 66.04,53.85 SW1.7
  TOP w0.254: v1(66.96,42.5) U7.C5
  LYR4 w0.121: v1(66.96,42.5) 66.96,42.51 66.56,42.91 66.56,43.47 66.79,43.7 67.13,43.7 67.36,43.93 67.36,46.1
  LYR4 w0.133: 67.36,46.1 67.36,46.18 66.8,46.74 66.8,54.61 v1(67.31,55.12)
  BOTTOM w0.121: v1(67.31,55.12) R259.2
GPIO0-4: length 18.7
  TOP w0.121: v1(68.58,55.12) SW1.8
  TOP w0.254: v1(66.96,43.3) U7.C4
  LYR4 w0.121: 68.16,46.1 68.16,43.13 67.93,42.9 67.36,42.9 v1(66.96,43.3)
  LYR4 w0.133: 68.16,46.1 67.31,46.95 67.31,53.85 v1(68.58,55.12)
  BOTTOM w0.121: v1(68.58,55.12) R260.1
GPIO0-9: length 22.3
  TOP w0.121: Q5.5 v1(84.33,43.69)
  TOP w0.254: v1(66.16,42.5) U7.D5
  LYR3 w0.121: 68.96,43.43 68.71,43.43 68.17,42.9 66.56,42.9 v1(66.16,42.5)
  LYR3 w0.133: 68.96,43.43 75.44,43.43 75.95,42.93 83.57,42.93 v1(84.33,43.69)
  BOTTOM w0.121: v1(84.33,43.69) 85.09,42.93 R213.1
GPIO2-4: length 116.6
  TOP w0.121: v1(74.93,41.91) 74.42,41.4 73.53,41.4 73.28,41.15 71.12,41.15 69.09,39.12 68.71,39.12 68.49,38.9 U7.A9
  LYR3 w0.133: v1(77.47,47.75) 73.15,52.07 31.62,52.07 27.81,48.26 27.81,41.53 24.64,38.35 22.86,38.35 22.1,37.59 15.24,37.59 14.73,37.08 14.73,36.58 12.7,34.54 9.78,34.54 8.59,33.35 S2.4
  LYR4 w0.133: v1(74.93,41.91) 75.18,41.91 75.69,42.42 75.69,43.31 75.44,43.56 75.44,45.72 v1(77.47,47.75)
  BOTTOM w0.121: S2.4 6.85,21.34 R220.2 6.1,22.1 5.12,23.08 S2.3
GPIO2-5: length 64.5
  TOP w0.254: v1(68.56,32.9) U7.A16
  LYR3 w0.121: v1(68.56,32.9) 68.95,32.9 68.96,32.89
  LYR3 w0.133: S3.4 96.1,11.43 99.06,11.43 99.57,11.94 99.57,28.7 98.81,29.46 83.06,29.46 82.04,30.48 77.34,30.48 76.83,30.99 70.87,30.99 68.96,32.89
  BOTTOM w0.121: S3.4 94.27,6.57 95,5.84 R221.2 95.76,4.58 S3.3
GPIO2-6: length 68.7
  TOP w0.121: U28.4 14.69,63.25 v1(15.49,63.25)
  TOP w0.254: v1(66.16,40.1) U7.D8
  LYR3 w0.133: v1(60.45,54.36) 59.18,53.09 30.99,53.09 24.64,59.44 19.05,59.44 18.03,60.45 18.03,60.96 17.02,61.98 16.26,61.98 15.49,62.74 v1(15.49,63.25)
  BOTTOM w0.121: v1(60.45,54.36) 63.14,51.66 63.14,45.75 64.39,44.5 64.73,44.5 64.96,44.27 64.96,43.93 65.19,43.7 65.53,43.7 65.76,43.47 65.76,40.41 66.07,40.1 v1(66.16,40.1)
GPIO2-12: length 29.3
  TOP w0.121: Q5.2 v1(84.33,40.13)
  TOP w0.254: v1(62.96,32.9) U7.H16
  LYR3 w0.121: 68.96,38.86 68.33,38.86 65.76,36.3 65.76,35.93 65.53,35.7 65.16,35.7 64.96,35.5 64.96,34.23 64.03,33.3 63.53,33.3 63.13,32.9 v1(62.96,32.9)
  LYR3 w0.133: 68.96,38.86 76.45,38.86 77.47,37.85 78.23,37.85 80.01,39.62 83.82,39.62 v1(84.33,40.13)
  BOTTOM w0.121: v1(84.33,40.13) 83.57,40.89 R212.1
GPIO4-0: length 47.6
  TOP w0.121: v1(57.52,77.72) 57.4,77.84 R44.2
  TOP w0.254: v1(65.36,36.1) U7.E12
  LYR4 w0.121: 64.26,46.1 64.26,45.97 64.16,45.87 64.16,38.2 64.96,37.4 64.96,36.89 U7.E12 v1(65.36,36.1)
  LYR4 w0.133: v1(57.52,77.72) 58.93,76.32 58.93,73.79 61.72,70.99 61.72,59.44 63.75,57.4 63.75,50.04 64.26,49.53 64.26,46.1
  BOTTOM w0.121: v1(57.52,77.72) J4.10
GPIO6-8: length 70.3
  TOP w0.121: U26.D3 13.21,9.13 v1(13.21,12.19)
  TOP w0.254: v1(55.76,33.7) U7.T15
  LYR3 w0.133: v1(36.83,25.4) 35.56,26.67 28.45,26.67 18.29,16.51 11.56,16.51 10.92,15.88 10.92,12.45 11.68,11.68 12.7,11.68 v1(13.21,12.19)
  BOTTOM w0.121: v1(55.76,33.7) 55.76,32.91 55.36,32.51 55.36,30.34 54.74,29.72 54.74,27.18 54.23,26.67 45.21,26.67 43.12,28.77 37.66,28.77 37.34,28.45 37.34,25.91 v1(36.83,25.4)
GPIO6-9: length 13.5
  TOP w0.121: R194.1 v1(51.82,22.86)
  TOP w0.254: v1(54.96,32.9) U7.U16
  LYR4 w0.133: v1(54.96,32.9) 54.48,32.42 54.48,31.62 54.61,31.5 54.61,29.46 52.45,27.3 52.45,23.5 v1(51.82,22.86)
  BOTTOM w0.121: v1(51.82,22.86) R194.1
GPIO6-10: length 13.2
  TOP w0.121: U7.W15 53.63,34.1 52.01,32.48 52.01,28.64 49.53,26.16 v1(49.53,25.4) R193.1
  BOTTOM w0.121: v1(49.53,25.4) 48.51,25.4 48.26,25.15 R196.2
GPIO6-11: length 12.1
  TOP w0.121: R192.1 v1(53.09,22.86)
  TOP w0.254: v1(54.96,32.1) U7.U17
  LYR4 w0.133: v1(53.09,22.86) 54.61,24.38 54.61,28.99 54.96,29.34 v1(54.96,32.1)
  BOTTOM w0.121: v1(53.09,22.86) R192.1
GPIO8-10: length 35.7
  TOP w0.254: v1(64.56,44.9) U7.F2
  LYR3 w0.121: v1(64.56,44.9) 64.57,44.9 64.97,45.3 68.11,45.3 68.2,45.21 68.96,45.21
  LYR3 w0.133: 68.96,45.21 84.71,45.21 85.72,44.2 96.9,44.2 98.42,45.72
GPIO8-12: length 42.9
  TOP w0.254: v1(63.76,44.1) U7.G3
  LYR3 w0.121: v1(63.76,44.1) 64.14,44.48 64.14,45.85 64.39,46.1
  LYR3 w0.133: 64.39,46.1 64.52,46.23 86.87,46.23 88.65,44.45 96.52,44.45 97.41,45.34 97.41,49.78 98.42,50.8
HS/CS/GPIO: length 13.2
  TOP w0.121: U21.72 30.21,19.57 v1(29.97,19.81)
  LYR4 w0.133: v1(29.97,19.81) 29.46,20.32 29.46,28.45 30.48,29.46 TP11.1
INTN: length 27.3
  TOP w0.121: R187.1 v1(81.28,64.77) ; U7.A1 68.58,45.72 68.58,45.97 73.15,50.55 73.15,56.77 v1(75.18,58.8)
  LYR3 w0.133: v1(75.18,58.8) 75.18,60.71 77.47,62.99 80.26,62.99 81.28,64.01 v1(81.28,64.77)
INTREQ: length 6.8
  TOP w0.121: U21.30 46.48,20.07 46.74,19.82 46.74,17.27 TP15.1
LAN_XTAL1: length 4.8
  TOP w0.121: U23.5 72.39,70.87 71.88,70.36 R190.1 71.63,70.87 71.63,71.37 R191.1
LAN_XTAL2: length 7.9
  TOP w0.121: R191.2 68.85,72.9 Y6.1 ; R191.2 v1(71.12,73.66) ; R191.2 71.63,72.9 71.88,72.64 71.88,71.88 72.39,71.37 U23.4
  BOTTOM w0.121: R191.2 v1(71.12,73.66)
LCD_1V8_D_0: length 58.9
  TOP w0.121: U14.47 32.85,59.31 32.72,59.18 32,59.18 31.88,59.31 31.88,61.09 31.75,61.21 28.61,61.21 26.07,58.67 v1(24.38,58.67) 23.88,59.18 10.92,59.18 9.53,57.78 7.11,57.78 6.22,58.67 6.22,64.9 6.1,65.02 5.46,65.02 5.33,64.9 5.33,61.47 5.21,61.34 P1.5 ; U13.5 22.36,48.78 v1(22.86,49.28) ; U13.10 22.32,51.28 v1(22.86,51.82)
  LYR4 w0.133: v1(22.86,51.82) 22.86,53.34 24.39,54.87 24.39,58.17 v1(24.38,58.67)
  BOTTOM w0.121: v1(22.86,51.82) 23.37,51.31 23.37,49.78 v1(22.86,49.28)
LCD_1V8_D_1: length 59.5
  TOP w0.121: U14.46 33.35,59.31 32.98,58.93 31.88,58.93 31.63,59.18 31.63,60.83 31.5,60.96 28.7,60.96 25.91,58.17 23.88,58.17 v1(23.62,58.42) 23.11,58.93 11.05,58.93 9.65,57.53 6.99,57.53 6.54,57.97 1.65,57.97 1.52,58.1 1.52,63.37 1.65,63.5 2.16,63.5 2.29,63.37 2.29,62.74 2.41,62.61 P1.8 ; U13.9 22.08,50.78 v1(22.1,50.8) ; U13.4 22.08,48.28 v1(22.1,48.26)
  LYR4 w0.133: v1(22.1,50.8) 21.59,51.31 21.59,52.83 21.84,53.09 22.1,53.09 23.62,54.61 v1(23.62,58.42)
  BOTTOM w0.121: v1(22.1,48.26) 21.59,48.77 21.59,50.29 v1(22.1,50.8)
LCD_1V8_D_2: length 62.3
  TOP w0.121: v1(22.86,48.26) 22.38,47.78 U13.3 ; U14.44 34.35,59.37 33.67,58.69 31.74,58.69 31.38,59.04 31.38,60.58 31.25,60.71 28.86,60.71 26.07,57.91 23.11,57.91 v1(22.86,58.17) 22.35,58.67 11.18,58.67 9.14,56.64 v1(8.64,56.64) ; v1(22.86,50.8) 22.34,50.28 U13.8
  LYR3 w0.133: v1(5.59,59.94) 5.59,61.34 P1.7
  LYR4 w0.133: v1(22.86,48.26) 23.37,48.77 23.37,50.29 v1(22.86,50.8) 23.37,51.31 23.37,51.82 23.62,52.07 24.38,52.07 24.89,52.58 24.89,58.93 24.64,59.18 23.37,59.18 23.11,58.93 23.11,58.42 v1(22.86,58.17) ; P1.4 3.68,60.71 4.83,60.71 v1(5.59,59.94) 5.59,59.31 7.24,57.66 7.62,57.66 v1(8.64,56.64)
LCD_1V8_D_3: length 63.3
  TOP w0.121: U14.43 34.85,59.31 33.98,58.44 31.6,58.44 31.11,58.93 31.11,59.31 30.86,59.56 28.07,59.56 26.16,57.66 22.35,57.66 22.1,57.91 v1(22.1,57.92) 21.85,58.17 11.56,58.17 v1(10.67,57.28) ; U13.2 21.59,47.28 21.81,47.5 22.86,47.5 23.37,48.01 23.37,49.53 v1(22.86,50.04) 22.6,49.78 U13.7
  LYR3 w0.133: P1.3 6.86,57.53 10.41,57.53 v1(10.67,57.28)
  LYR4 w0.133: v1(22.86,50.04) 22.1,50.04 21.34,50.8 21.34,56.52 22.1,57.28 v1(22.1,57.92) ; v1(10.67,57.28) 10.67,65.79 P2.15
LCD_1V8_D_4: length 61.2
  TOP w0.121: U13.1 19.51,46.78 19.3,46.99 19.3,49.02 19.56,49.28 U13.6 v1(22.1,49.28) ; v1(10.16,55.88) 11.94,57.66 v1(21.34,57.66) 21.59,57.4 26.32,57.4 28.22,59.31 30.73,59.31 30.86,59.18 30.86,58.8 31.47,58.19 35.27,58.19 35.85,58.78 U14.41
  LYR4 w0.133: v1(21.34,57.66) 21.08,57.4 21.08,50.3 v1(22.1,49.28) ; P1.6 3.68,61.98 4.83,61.98 5.84,62.99 5.84,63.5 6.86,64.52 8.13,64.52 P2.9 9.91,62.74 9.91,56.13 v1(10.16,55.88)
LCD_1V8_D_5: length 60.2
  TOP w0.121: U14.40 36.35,58.93 35.34,57.91 31.37,57.91 30.61,58.67 30.61,58.93 30.48,59.05 28.35,59.05 26.45,57.15 12.19,57.15 10.17,55.12 v1(10.17,55.12) 10.16,55.12 9.14,54.1 9.14,49.53 9.89,48.78 U13.32
  BOTTOM w0.121: v1(10.17,55.12) 9.4,55.12 8.13,56.39 8.13,56.77 6.73,58.17 4.83,58.17 4.57,57.91 2.54,57.91 1.52,58.93 1.52,65.66 1.65,65.79 2.16,65.79 2.29,65.66 2.29,64.64 P1.10
LCD_1V8_D_6: length 61.2
  TOP w0.121: U14.38 37.35,59.32 37.21,59.18 36.96,59.18 35.43,57.66 30.61,57.66 30.35,57.91 30.35,58.67 30.23,58.8 28.45,58.8 26.54,56.9 12.57,56.9 10.16,54.48 v1(10.16,53.85) 9.78,53.85 9.4,53.47 9.4,49.79 9.91,49.28 11.28,49.28 U13.31
  BOTTOM w0.121: v1(10.16,53.85) 7.87,56.13 7.87,56.64 6.6,57.91 4.95,57.91 4.7,57.66 2.29,57.66 1.27,58.67 1.27,65.91 P1.16
LCD_1V8_D_7: length 60.3
  TOP w0.121: U14.37 37.85,59.19 37.59,58.93 37.08,58.93 35.56,57.4 30.48,57.4 30.1,57.78 30.1,58.42 29.97,58.55 28.57,58.55 26.67,56.64 12.7,56.64 10.92,54.86 v1(10.92,53.85) 10.41,53.34 9.91,53.34 9.65,53.09 9.65,50.16 10.04,49.78 v1(10.92,49.78) U13.30 ; U13.36 11.13,46.78 v1(10.92,46.99)
  BOTTOM w0.121: v1(10.92,49.78) 10.93,49.78 11.43,49.28 11.43,47.5 v1(10.92,46.99) ; v1(10.92,53.85) 10.67,54.1 10.67,56.01 9.53,57.15 8.13,57.15 6.1,59.18 6.1,64.52 5.97,64.64 5.21,64.64 5.08,64.52 5.08,64.01 4.95,63.88 P1.9
LCD_1V8_D_8: length 63.3
  TOP w0.121: P2.10 6.48,62.87 6.48,58.8 7.24,58.04 9.4,58.04 10.79,59.44 26.42,59.44 29.15,62.17 37.4,62.17 38.35,61.22 U14.36 ; U13.35 11.39,47.28 v1(10.92,47.75) ; v1(10.16,50.28) U13.29
  LYR4 w0.133: v1(10.16,50.28) 9.14,51.3 9.14,56.77 8,57.91 7.37,57.91 6.6,58.67 6.6,62.99 P2.10
  BOTTOM w0.121: v1(10.92,47.75) 10.92,48.51 10.16,49.28 v1(10.16,50.28)
LCD_1V8_D_9: length 61.5
  TOP w0.121: U14.35 38.85,61.48 37.85,62.48 28.7,62.48 26.67,64.52 10.16,64.52 9.53,65.15 P2.11 ; U13.34 13.36,47.78 13.59,48.01 13.59,50.55 13.36,50.78 U13.28 11.2,50.78 v1(10.92,51.05)
  LYR4 w0.133: P1.12 3.68,65.79 8.13,65.79 P2.11 10.16,63.75 10.16,56.45 10.67,55.95 10.67,54.99 9.65,53.98 9.65,52.32 v1(10.92,51.05)
LCD_1V8_D_10: length 60.2
  TOP w0.121: v1(10.16,51.05) 10.67,51.56 11.05,51.56 11.33,51.28 U13.27 ; U13.33 10.69,48.28 v1(10.16,47.75) ; U14.33 39.85,61.88 38.99,62.74 28.96,62.74 26.92,64.77 10.41,64.77 P2.13
  LYR3 w0.133: P2.7 9.65,63.5 9.65,65.53 P2.13
  LYR4 w0.133: v1(10.16,51.05) 9.4,51.82 9.4,55.12 9.65,55.37 9.65,61.72 P2.7
  BOTTOM w0.121: v1(10.16,51.05) 9.65,50.55 9.65,48.26 v1(10.16,47.75)
LCD_1V8_D_11: length 60.3
  TOP w0.121: U13.13 19.26,54.57 19.56,54.86 v1(19.56,55.12) 20.07,55.63 20.07,56.13 20.32,56.39 26.8,56.39 28.7,58.29 29.72,58.29 29.84,58.17 29.84,57.78 29.72,57.66 28.7,57.66 28.57,57.53 28.57,57.28 28.7,57.15 35.69,57.15 37.21,58.67 39.88,58.67 40.13,58.93 40.13,59.18 40.35,59.4 U14.32 ; v1(17.53,55.88) 16.76,55.11 U13.18
  LYR3 w0.133: v1(17.53,55.88) 18.03,55.37 18.03,54.61 17.53,54.1 13.21,54.1 12.7,54.61 12.7,56.77 11.68,57.78 6.99,57.78 6.1,58.67 6.1,64.64 P1.13
  LYR4 w0.133: v1(17.53,55.88) 18.03,56.39 18.8,56.39 19.05,56.13 19.05,55.63 v1(19.56,55.12)
LCD_1V8_D_12: length 61.3
  TOP w0.121: U13.19 16.26,55.11 v1(15.49,55.88) ; U13.14 18.76,54.57 19.05,54.86 19.05,55.37 v1(19.56,55.88) ; v1(20.57,55.88) 20.83,56.13 29.21,56.13 29.97,56.9 35.81,56.9 37.34,58.42 41.22,58.42 41.35,58.55 U14.30
  LYR3 w0.133: v1(15.49,55.88) 16.89,55.88 17.02,56.01 17.02,56.26 16.89,56.39 15.62,56.39 15.49,56.52 15.49,56.77 15.62,56.9 16.89,56.9 17.02,57.02 17.02,57.28 16.89,57.4 15.62,57.4 15.49,57.53 15.49,57.78 15.62,57.91 16.26,57.91 16.38,58.04 16.38,58.55 13.08,61.85 9.78,61.85 9.65,61.72 9.65,61.47 9.78,61.34 11.3,61.34 11.43,61.21 11.43,60.96 11.3,60.83 9.78,60.83 9.65,60.71 9.65,60.45 9.78,60.33 11.3,60.33 11.43,60.2 11.43,59.94 11.3,59.82 9.02,59.82 P2.3
  BOTTOM w0.121: v1(15.49,55.88) 15.49,56.13 16,56.64 18.8,56.64 v1(19.56,55.88) v1(20.57,55.88)
LCD_1V8_D_13: length 60.4
  TOP w0.121: U13.20 15.75,53.64 15.75,54.86 v1(15.49,55.12) ; v1(18.54,55.12) 18.54,54.89 18.26,54.61 U13.15 ; U14.29 41.85,59.18 41.98,59.05 42.13,59.05 42.26,58.93 42.26,57.56 42.16,57.47 36.77,57.47 35.94,56.64 30.23,56.64 28.45,54.86 23.75,54.86 23.62,54.99 23.62,55.24 23.75,55.37 28.19,55.37 28.32,55.5 28.32,55.75 28.19,55.88 21.34,55.88 v1(20.57,55.12) ; P2.4 6.73,60.83 6.73,61.85 P2.8
  LYR3 w0.133: P2.4 8.13,59.44 12.19,59.44 14.99,56.64 14.99,55.63 v1(15.49,55.12) ; v1(20.57,55.12) 20.07,54.61 19.05,54.61 v1(18.54,55.12)
  BOTTOM w0.121: v1(18.54,55.12) 18.03,55.63 18.03,56.13 17.78,56.39 16.24,56.39 15.89,56.05 15.89,55.52 v1(15.49,55.12)
LCD_1V8_D_14: length 61.5
  TOP w0.121: U14.27 42.85,58.5 43.18,58.17 43.18,57.34 43.05,57.21 36.89,57.21 36.07,56.39 30.35,56.39 28.57,54.61 23.5,54.61 23.37,54.74 23.37,55.5 23.24,55.63 22.73,55.63 22.23,55.12 v1(22.1,55.12) ; U13.21 15.26,52.56 15.49,52.32 17.51,52.32 17.76,52.58 U13.16 17.76,54.59 18.03,54.86 18.03,55.37 v1(18.54,55.88)
  LYR3 w0.133: P1.14 3.68,67.06 4.83,67.06 6.35,65.53 6.35,62.61 6.99,61.98 8.13,61.98 P2.5 9.65,62.23 13.21,62.23 18.03,57.4 18.03,56.39 v1(18.54,55.88) 19.05,56.39 20.83,56.39 v1(22.1,55.12)
LCD_1V8_D_15: length 61.1
  TOP w0.121: U13.22 14.76,55.22 14.22,55.75 v1(14.22,55.88) ; U13.17 17.26,54.85 v1(17.53,55.12) ; U14.26 43.35,58.55 43.48,58.42 45.05,58.42 45.18,58.29 45.18,57.4 44.73,56.96 37.02,56.96 36.2,56.13 30.48,56.13 28.7,54.36 22.99,54.36 22.86,54.48 v1(22.86,55.12)
  LYR3 w0.133: P2.6 6.73,60.58 6.73,58.42 7.11,58.04 12.06,58.04 v1(14.22,55.88) 14.73,55.37 14.73,54.86 15.24,54.36 16.76,54.36 v1(17.53,55.12)
  BOTTOM w0.121: v1(22.86,55.12) 22.35,54.61 18.03,54.61 v1(17.53,55.12) ; P2.6 6.6,62.23 6.6,64.52 5.97,65.15 P1.11
LCD_AC_ENB_CSN: length 60.4
  TOP w0.121: U12.6 18.03,62.74 18.29,62.48 v1(19.05,62.48)
  TOP w0.254: v1(57.36,41.7) U7.R5
  LYR3 w0.133: v1(19.05,62.48) 18.54,61.98 18.54,60.45 19.3,59.69 24.89,59.69 31.24,53.34 55.37,53.34 55.88,53.85 v1(55.88,54.36)
  LYR4 w0.121: 59.18,46.1 59.18,44.45 58.56,43.83 58.56,42.9 v1(57.36,41.7)
  LYR4 w0.133: 59.18,46.1 59.18,51.05 v1(55.88,54.36)
LCD_AC_ENB_CSN_1V8: length 25.2
  TOP w0.121: U13.23 v1(14.26,55.12) ; v1(16.51,62.48) 16.76,62.48 18.03,61.22 U12.3
  LYR3 w0.133: P2.17 9.78,68.96 11.94,66.8 12.7,66.8 16,63.5 16,62.99 v1(16.51,62.48)
  LYR4 w0.133: v1(14.26,55.12) 14.73,55.59 14.73,57.66 17.02,59.94 17.02,61.98 v1(16.51,62.48)
  BOTTOM w0.121: R100.1 14.73,54.65 v1(14.26,55.12)
LCD_BLUE: length 19.4
  TOP w0.121: J8.3 4.57,41.66 7.49,38.73 15.88,38.73 v1(16.51,39.37) 16.83,39.69 L6.2
  BOTTOM w0.121: v1(16.51,39.37) C115.2 C113.1
LCD_BLUE_N: length 10.6
  TOP w0.121: v1(19.05,41.91) 18.73,41.59 L6.1 17.76,41.61 U13.45
  BOTTOM w0.121: R122.1 v1(19.05,41.91) C114.2 C113.2
LCD_GREEN: length 8.8
  TOP w0.121: L4.2 9.84,39.37 v1(8.89,39.37)
  LYR3 w0.133: J8.2 v1(8.89,39.37)
  BOTTOM w0.121: v1(8.89,39.37) C109.2 C105.1
LCD_GREEN_N: length 13.5
  TOP w0.121: L4.1 11.11,41.59 v1(11.43,41.91) 12.7,43.18 15.24,43.18 15.76,43.7 U13.41
  BOTTOM w0.121: C105.2 C108.2 v1(11.43,41.91) R118.2
LCD_HSYNC/MMCSD1_D5: length 65.7
  TOP w0.121: v1(26.67,61.47) 26.17,61.47 25.15,62.48 U24.7 ; U15.7 25.15,52.58 26.17,51.56 v1(26.67,51.56)
  TOP w0.254: v1(62.96,43.3) U7.H4
  LYR3 w0.133: v1(62.23,54.36) 60.45,52.58 27.69,52.58 v1(26.67,51.56)
  LYR4 w0.121: v1(62.96,43.3) 62.87,43.3 62.56,43.61 62.56,44.27 62.79,44.5 63.13,44.5 63.36,44.73 63.36,46.1
  LYR4 w0.133: v1(62.23,54.36) 62.99,53.59 62.99,47.87 63.36,47.5 63.36,46.1 ; v1(26.67,51.56) 27.18,52.07 27.18,60.96 v1(26.67,61.47)
LCD_HSYNC_1V8: length 25.6
  TOP w0.121: v1(24.13,61.47) 24.89,61.47 25.15,61.21 U24.2
  LYR3 w0.133: v1(24.13,61.47) 23.62,61.47 21.34,63.75 17.27,63.75 10.67,70.36 9.65,70.36 8.89,71.12 7.05,71.12 6.6,70.68 6.6,69.85 P2.18
LCD_HSYNC_5V: length 31
  TOP w0.121: U15.2 25.15,51.3 24.89,51.56 v1(24.13,51.56)
  LYR3 w0.133: J8.13 10.41,40.89 10.92,41.4 20.57,41.4 22.1,42.93 22.61,42.93 23.62,43.94 23.62,51.05 v1(24.13,51.56)
LCD_PCLK/MMCSD1_D7: length 60.6
  TOP w0.121: U12.7 17.53,62.23 18.29,61.47 v1(19.05,61.47)
  TOP w0.254: v1(64.56,45.7) U7.F1
  LYR3 w0.133: v1(63.12,55.12) 62.61,55.63 58.17,55.63 57.15,56.64 28.7,56.64 25.4,59.94 20.07,59.94 19.56,60.45 19.56,60.96 v1(19.05,61.47)
  BOTTOM w0.121: v1(64.56,45.7) 64.39,45.87 64.39,53.85 v1(63.12,55.12)
LCD_PCLK_1V8: length 37
  TOP w0.121: U13.26 11.21,51.78 v1(10.16,52.83) ; U12.2 17.53,61.21 17.27,61.47 v1(16.51,61.47)
  LYR4 w0.133: v1(10.16,52.83) 10.67,53.34 11.68,53.34 12.95,54.61 12.95,57.15 16,60.2 16,60.96 v1(16.51,61.47) 12.45,65.53 12.45,70.36 v1(11.18,71.63)
  BOTTOM w0.121: P2.16 6.6,68.58 6.6,70.61 7.11,71.12 10.67,71.12 v1(11.18,71.63)
LCD_RED: length 15.5
  TOP w0.121: L5.2 13.65,39.37 v1(12.7,39.37)
  LYR3 w0.121: 3.81,37.08 J8.1
  LYR3 w0.133: 3.81,37.08 7.87,37.08 10.67,39.88 12.19,39.88 v1(12.7,39.37)
  BOTTOM w0.121: C110.1 C112.2 v1(12.7,39.37)
LCD_RED_N: length 8.9
  TOP w0.121: U13.43 16.76,44.19 v1(16.51,43.94) 16.51,43.18 v1(15.24,41.91) 14.92,41.59 L5.1
  BOTTOM w0.121: v1(15.24,41.91) C111.2 C110.2 ; v1(16.51,43.94) R119.2
LCD_SCL: length 26.4
  TOP w0.121: U25.5 22.66,63.45 v1(22.86,63.25)
  LYR3 w0.133: P2.14 6.1,67.82 6.1,70.61 6.86,71.37 9.14,71.37 9.91,70.61 11.94,70.61 12.7,69.85 12.7,68.83 17.53,64.01 22.1,64.01 v1(22.86,63.25)
